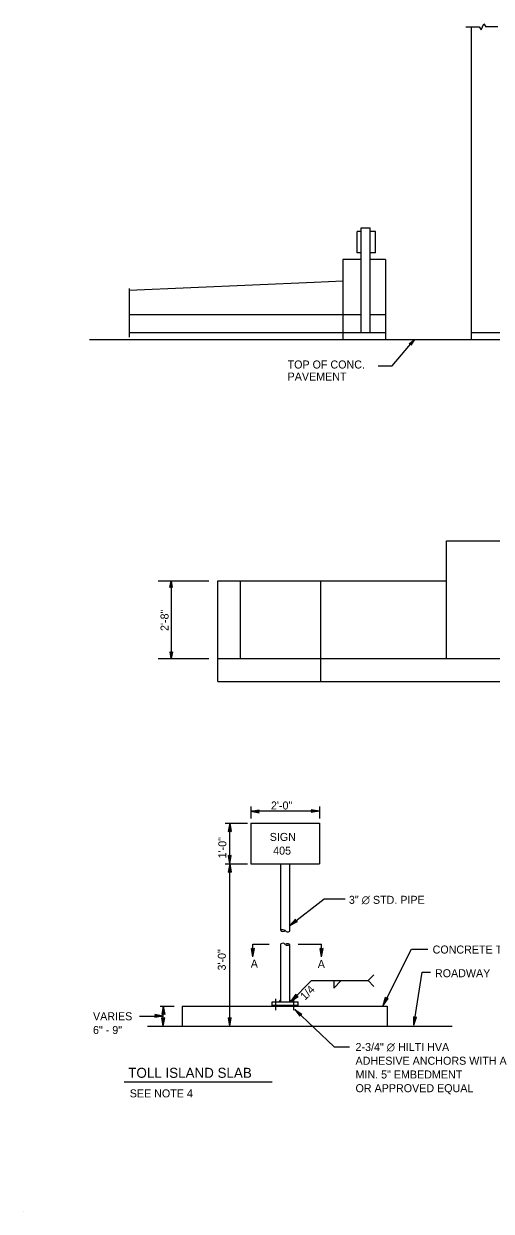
# Model space of a CAD drawing. Extents: x -63400 to -62632, y -1624834 to -1624417.
# Drawn here: x -63399.5 to -63236.2, y -1624834.2 to -1624418.8 of the extents above; entities that cross this region are included whole.
import ezdxf

# ---------------------------------------------------------------- set-up
doc = ezdxf.new("R2010")
doc.units = 0
for name, color, linetype in [('1', 7, 'Continuous'), ('15', 7, 'Continuous'), ('21', 7, 'Continuous'), ('33', 7, 'Continuous'), ('52', 7, 'Continuous'), ('AdhocPoint_dp', 7, 'Continuous'), ('LeaderLine_dp', 7, 'Continuous'), ('SignPanel', 7, 'Continuous'), ('TextDetails', 7, 'Continuous'), ('TextLabel', 7, 'Continuous')]:
    doc.layers.add(name, color=color, linetype=linetype)

# ---------------------------------------------------------------- blocks, each defined once
blk = doc.blocks.new('BREAK2')
at = {"layer": '21'}
for p, q in [((-3.324, 0), (-0.737, 0)), ((-0.283, -0.653), (-0.737, 0)), ((0.283, 0.654), (-0.283, -0.653)), ((0.738, 0), (0.283, 0.654)), ((3.67, 0), (0.738, 0))]:
    blk.add_line(p, q, dxfattribs=at)
blk = doc.blocks.new('20T21')
at = {"layer": '21'}
for p, q in [((0, 0), (-2.915, -0.514)), ((-2.692, 0), (-2.915, -0.514)), ((0, 0), (-2.914, 0.515)), ((-2.914, 0.515), (-2.692, 0)), ((0, 0), (-2.798, 0.244)), ((0, 0), (-2.796, -0.244))]:
    blk.add_line(p, q, dxfattribs=at)
blk = doc.blocks.new('T52')
at = {"layer": '52'}
blk.add_lwpolyline([(0, 0), (-0.146, -0.023), (-0.135, 0.002), (-0.145, 0.028)], close=True, dxfattribs=at)

msp = doc.modelspace()

# ---------------------------------------------------------------- linework, layer by layer
at = {"layer": '1'}
for p, q in [((-63309.74, -1624735.99), (-63309.74, -1624712.71)), ((-63306.6, -1624736.21), (-63306.6, -1624712.71)), ((-63309.74, -1624760.93), (-63309.74, -1624740.68)), ((-63306.6, -1624760.93), (-63306.6, -1624740.9)), ((-63312.74, -1624760.93), (-63303.6, -1624760.93)), ((-63312.74, -1624762.49), (-63312.74, -1624760.93)), ((-63312.74, -1624762.12), (-63303.6, -1624762.12)), ((-63310.27, -1624760.93), (-63309.74, -1624760.25)), ((-63310.18, -1624760.93), (-63309.74, -1624760.36)), ((-63310.11, -1624760.93), (-63309.74, -1624760.46)), ((-63310.03, -1624760.93), (-63309.74, -1624760.55)), ((-63309.94, -1624760.93), (-63309.74, -1624760.67)), ((-63309.86, -1624760.93), (-63309.74, -1624760.77)), ((-63306.07, -1624760.93), (-63306.6, -1624760.25)), ((-63306.16, -1624760.93), (-63306.6, -1624760.36)), ((-63306.23, -1624760.93), (-63306.6, -1624760.46)), ((-63306.31, -1624760.93), (-63306.6, -1624760.55)), ((-63306.4, -1624760.93), (-63306.6, -1624760.67)), ((-63306.48, -1624760.93), (-63306.6, -1624760.77)), ((-63303.6, -1624762.49), (-63303.6, -1624760.93)), ((-63344.17, -1624762.49), (-63272.56, -1624762.49)), ((-63344.17, -1624762.49), (-63344.17, -1624769.49)), ((-63272.56, -1624762.49), (-63272.56, -1624769.49)), ((-63356.25, -1624769.49), (-63249.85, -1624769.49))]:
    msp.add_line(p, q, dxfattribs=at)
for centre, radius, start, end in [((-63309, -1624736.96), 1.21, 49.1009, 127.2256), ((-63308.94, -1624735.07), 1.22, 229.2404, 307.0862), ((-63307.32, -1624735.3), 1.16, 219.7646, 308.095), ((-63309.02, -1624741.6), 1.16, 39.7646, 128.095), ((-63307.4, -1624741.82), 1.22, 49.2404, 127.0862), ((-63307.33, -1624739.94), 1.21, 229.1009, 307.2256)]:
    msp.add_arc(centre, radius, start, end, dxfattribs=at)
at = {"layer": '15'}
for p, q in [((-63281.59, -1624490.1), (-63278.47, -1624490.1)), ((-63281.59, -1624501.19), (-63281.59, -1624490.1)), ((-63278.47, -1624501.19), (-63278.47, -1624490.1)), ((-63281.59, -1624526.53), (-63281.59, -1624501.2)), ((-63278.47, -1624526.53), (-63278.47, -1624501.2))]:
    msp.add_line(p, q, dxfattribs=at)
at = {"layer": '21'}
for p, q in [((-63251.75, -1624640.83), (-63251.75, -1624599.63)), ((-63251.75, -1624599.63), (-63217.14, -1624599.63)), ((-63331.75, -1624648.83), (-63331.75, -1624613.63)), ((-63331.75, -1624613.63), (-63251.75, -1624613.63)), ((-63323.75, -1624640.83), (-63323.75, -1624613.63)), ((-63295.75, -1624648.83), (-63295.75, -1624613.63)), ((-63331.75, -1624640.83), (-63295.75, -1624640.83)), ((-63295.75, -1624640.83), (-62837.14, -1624640.83)), ((-63331.75, -1624648.83), (-62817.14, -1624648.83))]:
    msp.add_line(p, q, dxfattribs=at)
at = {"layer": '33'}
for p, q in [((-63243.22, -1624419.86), (-63243.22, -1624529.2)), ((-63283.05, -1624498.91), (-63283.05, -1624491.44)), ((-63281.54, -1624491.44), (-63283.05, -1624491.44)), ((-63276.64, -1624491.44), (-63278.47, -1624491.44)), ((-63276.64, -1624498.91), (-63276.64, -1624491.44)), ((-63281.59, -1624498.91), (-63283.05, -1624498.91)), ((-63276.64, -1624498.91), (-63278.47, -1624498.91)), ((-63288.04, -1624501.19), (-63288.04, -1624529.2)), ((-63281.68, -1624501.19), (-63288.04, -1624501.19)), ((-63273.1, -1624501.19), (-63278.47, -1624501.19)), ((-63273.1, -1624501.19), (-63273.1, -1624529.2)), ((-63298.06, -1624509.11), (-63288.04, -1624508.67)), ((-63362.72, -1624511.99), (-63298.06, -1624509.11)), ((-63362.72, -1624511.34), (-63362.72, -1624528.38)), ((-63362.88, -1624520.46), (-63298.06, -1624520.46)), ((-63298.06, -1624520.46), (-63281.61, -1624520.46)), ((-63278.55, -1624520.46), (-63273.1, -1624520.46)), ((-63376.53, -1624529.2), (-63003.79, -1624529.2)), ((-63362.88, -1624526.74), (-63273.1, -1624526.74)), ((-63243.22, -1624526.74), (-63006.61, -1624526.74))]:
    msp.add_line(p, q, dxfattribs=at)
at = {"layer": 'AdhocPoint_dp'}
msp.add_line((-63399.55, -1624834.21), (-63399.55, -1624834.21), dxfattribs=at)
at = {"layer": 'LeaderLine_dp'}
for p, q in [((-63270.77, -1624538.43), (-63263.01, -1624529.2)), ((-63275.7, -1624538.43), (-63270.77, -1624538.43)), ((-63352.62, -1624613.63), (-63334.91, -1624613.63)), ((-63348.01, -1624613.63), (-63348.01, -1624640.83)), ((-63352.62, -1624640.83), (-63334.91, -1624640.83)), ((-63320.17, -1624692.55), (-63320.17, -1624696.83)), ((-63320.17, -1624694.29), (-63317.24, -1624693.82)), ((-63320.17, -1624694.29), (-63317.37, -1624694.09)), ((-63296.17, -1624694.29), (-63320.17, -1624694.29)), ((-63320.17, -1624694.29), (-63317.26, -1624694.85)), ((-63320.17, -1624694.29), (-63317.37, -1624694.58)), ((-63317.47, -1624694.33), (-63317.24, -1624693.82)), ((-63317.26, -1624694.85), (-63317.47, -1624694.33)), ((-63298.86, -1624694.24), (-63299.09, -1624694.75)), ((-63296.17, -1624694.29), (-63299.09, -1624694.75)), ((-63296.17, -1624694.29), (-63299.07, -1624693.72)), ((-63299.07, -1624693.72), (-63298.86, -1624694.24)), ((-63296.17, -1624694.29), (-63298.97, -1624694.48)), ((-63296.17, -1624694.29), (-63298.96, -1624693.99)), ((-63296.17, -1624692.55), (-63296.17, -1624696.83)), ((-63329.14, -1624698.4), (-63321.4, -1624698.4)), ((-63327.58, -1624698.4), (-63328.14, -1624701.3)), ((-63327.58, -1624698.4), (-63327.87, -1624701.19)), ((-63327.58, -1624712.71), (-63327.58, -1624698.4)), ((-63327.58, -1624698.4), (-63327.11, -1624701.32)), ((-63327.58, -1624698.4), (-63327.38, -1624701.2)), ((-63328.14, -1624701.3), (-63327.62, -1624701.09)), ((-63327.62, -1624701.09), (-63327.11, -1624701.32)), ((-63327.58, -1624712.71), (-63328.04, -1624709.78)), ((-63327.53, -1624710.01), (-63328.04, -1624709.78)), ((-63327.58, -1624712.71), (-63327.77, -1624709.91)), ((-63327.58, -1624712.71), (-63327.01, -1624709.8)), ((-63327.58, -1624712.71), (-63327.29, -1624709.91)), ((-63327.01, -1624709.8), (-63327.53, -1624710.01)), ((-63329.14, -1624712.71), (-63321.4, -1624712.71)), ((-63327.58, -1624712.71), (-63328.14, -1624715.61)), ((-63328.14, -1624715.61), (-63327.62, -1624715.4)), ((-63327.58, -1624712.71), (-63327.87, -1624715.5)), ((-63327.62, -1624715.4), (-63327.11, -1624715.63)), ((-63327.58, -1624769.49), (-63327.58, -1624712.71)), ((-63327.58, -1624712.71), (-63327.11, -1624715.63)), ((-63327.58, -1624712.71), (-63327.38, -1624715.51)), ((-63306.55, -1624734.21), (-63294.59, -1624724.96)), ((-63294.59, -1624724.96), (-63287.26, -1624724.96)), ((-63306.55, -1624734.21), (-63304.52, -1624732.05)), ((-63306.55, -1624734.21), (-63304.46, -1624732.34)), ((-63306.55, -1624734.21), (-63304.16, -1624732.73)), ((-63306.55, -1624734.21), (-63303.91, -1624732.88)), ((-63304.4, -1624732.6), (-63304.52, -1624732.05)), ((-63303.91, -1624732.88), (-63304.4, -1624732.6)), ((-63319.46, -1624745.19), (-63319.46, -1624740.74)), ((-63319.46, -1624740.74), (-63313.73, -1624740.74)), ((-63303.6, -1624740.74), (-63295.46, -1624740.74)), ((-63295.46, -1624745.2), (-63295.46, -1624740.74)), ((-63319.46, -1624745.19), (-63319.93, -1624742.27)), ((-63319.42, -1624742.5), (-63319.93, -1624742.27)), ((-63319.46, -1624745.19), (-63319.66, -1624742.39)), ((-63319.46, -1624745.19), (-63318.9, -1624742.29)), ((-63319.46, -1624745.19), (-63319.17, -1624742.4)), ((-63318.9, -1624742.29), (-63319.42, -1624742.5)), ((-63295.46, -1624745.2), (-63295.93, -1624742.27)), ((-63295.42, -1624742.5), (-63295.93, -1624742.27)), ((-63295.46, -1624745.2), (-63295.66, -1624742.4)), ((-63295.46, -1624745.2), (-63294.9, -1624742.29)), ((-63295.46, -1624745.2), (-63295.17, -1624742.4)), ((-63294.9, -1624742.29), (-63295.42, -1624742.5)), ((-63273.9, -1624762.19), (-63264.07, -1624742.5)), ((-63264.07, -1624742.5), (-63258.28, -1624742.5)), ((-63306.13, -1624760.69), (-63298.95, -1624753.51)), ((-63298.95, -1624753.51), (-63279.18, -1624753.51)), ((-63291.19, -1624753.51), (-63291.19, -1624756.18)), ((-63291.19, -1624756.18), (-63288.55, -1624753.51)), ((-63279.18, -1624753.51), (-63277.15, -1624751.45)), ((-63279.18, -1624753.51), (-63277.15, -1624755.56)), ((-63263.2, -1624769.14), (-63260.31, -1624750.61)), ((-63260.31, -1624750.61), (-63257.41, -1624750.61)), ((-63311.43, -1624763.85), (-63311.43, -1624759.95)), ((-63306.13, -1624760.69), (-63304.39, -1624758.29)), ((-63306.13, -1624760.69), (-63304.29, -1624758.57)), ((-63306.13, -1624760.69), (-63303.95, -1624758.92)), ((-63306.13, -1624760.69), (-63303.68, -1624759.03)), ((-63305.1, -1624763.85), (-63305.1, -1624759.95)), ((-63304.2, -1624758.82), (-63304.39, -1624758.29)), ((-63303.68, -1624759.03), (-63304.2, -1624758.82)), ((-63359.04, -1624765.94), (-63350.87, -1624765.94)), ((-63351.9, -1624762.49), (-63347, -1624762.49)), ((-63350.87, -1624762.47), (-63351.33, -1624765.39)), ((-63350.82, -1624765.16), (-63351.33, -1624765.39)), ((-63350.87, -1624762.47), (-63351.06, -1624765.27)), ((-63350.87, -1624762.47), (-63350.3, -1624765.37)), ((-63350.87, -1624762.47), (-63350.58, -1624765.26)), ((-63350.87, -1624769.49), (-63350.87, -1624762.49)), ((-63350.3, -1624765.37), (-63350.82, -1624765.16)), ((-63304.86, -1624763.65), (-63291.08, -1624776.69)), ((-63304.86, -1624763.65), (-63302.38, -1624765.26)), ((-63304.86, -1624763.65), (-63303.08, -1624766.01)), ((-63304.86, -1624763.65), (-63302.98, -1624765.73)), ((-63304.86, -1624763.65), (-63302.65, -1624765.37)), ((-63303.08, -1624766.01), (-63302.89, -1624765.48)), ((-63302.89, -1624765.48), (-63302.38, -1624765.26)), ((-63350.87, -1624769.49), (-63351.33, -1624766.57)), ((-63350.82, -1624766.8), (-63351.33, -1624766.57)), ((-63350.87, -1624769.49), (-63351.06, -1624766.69)), ((-63350.87, -1624769.49), (-63350.3, -1624766.58)), ((-63350.87, -1624769.49), (-63350.58, -1624766.7)), ((-63350.3, -1624766.58), (-63350.82, -1624766.8)), ((-63327.58, -1624769.49), (-63328.04, -1624766.57)), ((-63327.53, -1624766.8), (-63328.04, -1624766.57)), ((-63327.58, -1624769.49), (-63327.77, -1624766.69)), ((-63327.58, -1624769.49), (-63327.01, -1624766.58)), ((-63327.58, -1624769.49), (-63327.29, -1624766.7)), ((-63327.01, -1624766.58), (-63327.53, -1624766.8)), ((-63291.08, -1624776.69), (-63285.73, -1624776.69))]:
    msp.add_line(p, q, dxfattribs=at)
at = {"layer": 'SignPanel'}
for p, q in [((-63320.17, -1624698.4), (-63320.17, -1624712.71)), ((-63320.17, -1624698.4), (-63296.17, -1624698.4)), ((-63296.17, -1624698.4), (-63296.17, -1624712.71)), ((-63320.17, -1624712.71), (-63296.17, -1624712.71))]:
    msp.add_line(p, q, dxfattribs=at)
at = {"layer": 'TextDetails'}
msp.add_line((-63364.41, -1624788.98), (-63312.67, -1624788.98), dxfattribs=at)

# ---------------------------------------------------------------- block references
at = {"layer": '21', "xscale": 1.6, "yscale": 1.6000000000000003, "rotation": 180}
msp.add_blockref('BREAK2', (-63239.18, -1624419.8), dxfattribs=at)
at = {"layer": 'LeaderLine_dp', "xscale": 16, "yscale": 16}
for p, rotation in [((-63263.01, -1624529.2), 49.91570705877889), ((-63348.01, -1624613.63), 90), ((-63348.01, -1624640.83), -90)]:
    msp.add_blockref('T52', p, dxfattribs=dict(at, rotation=rotation))
at = {"layer": 'LeaderLine_dp'}
for p, rotation in [((-63273.9, -1624762.19), -116.54176730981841), ((-63263.2, -1624769.14), -98.87018946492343)]:
    msp.add_blockref('20T21', p, dxfattribs=dict(at, rotation=rotation))
msp.add_blockref('20T21', (-63350.87, -1624765.94), dxfattribs=at)

# ---------------------------------------------------------------- texts
at = {"layer": 'SignPanel'}
for s, p in [('SIGN', (-63313.58, -1624704.65)), ('405', (-63312.38, -1624709.45))]:
    msp.add_text(s, height=2.8, dxfattribs=at).set_placement(p)
at = {"layer": 'TextDetails'}
for s, height, p in [('TOLL ISLAND SLAB', 3.5, (-63363.03, -1624787.53)), ('SEE NOTE 4', 2.8, (-63362.5, -1624794.38))]:
    msp.add_text(s, height=height, dxfattribs=at).set_placement(p)
at = {"layer": 'TextLabel'}
for s, p in [('TOP OF CONC.', (-63307.33, -1624539.37)), ('PAVEMENT', (-63307.33, -1624543.57)), ('2\'-0"', (-63313.15, -1624693.65)), ('3" ∅ STD. PIPE', (-63285.9, -1624726.66)), ('CONCRETE TOLL ISLAND', (-63256.65, -1624744.05)), ('A', (-63320.21, -1624748.99)), ('A', (-63296.79, -1624749.13)), ('ROADWAY', (-63255.82, -1624752.34)), ('VARIES', (-63375.35, -1624767.4)), ('6" - 9"', (-63375.35, -1624772.2)), ('2-3/4" ∅ HILTI HVA', (-63283.59, -1624778.16)), ('ADHESIVE ANCHORS WITH A', (-63283.59, -1624782.96)), ('MIN. 5" EMBEDMENT', (-63283.59, -1624787.76)), ('OR APPROVED EQUAL', (-63283.59, -1624792.56))]:
    msp.add_text(s, height=2.8, dxfattribs=at).set_placement(p)
for s, rotation, p in [('2\'-8"', 90, (-63348.95, -1624631.21)), ('1\'-0"', 90, (-63328.75, -1624710.76)), ('3\'-0"', 90, (-63328.93, -1624749.99)), ('1/4', 45.0279, (-63301.27, -1624760.57))]:
    msp.add_text(s, height=2.8, rotation=rotation, dxfattribs=at).set_placement(p)

doc.saveas('drawing.dxf')
